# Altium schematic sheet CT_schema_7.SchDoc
size 391 x 238 mm
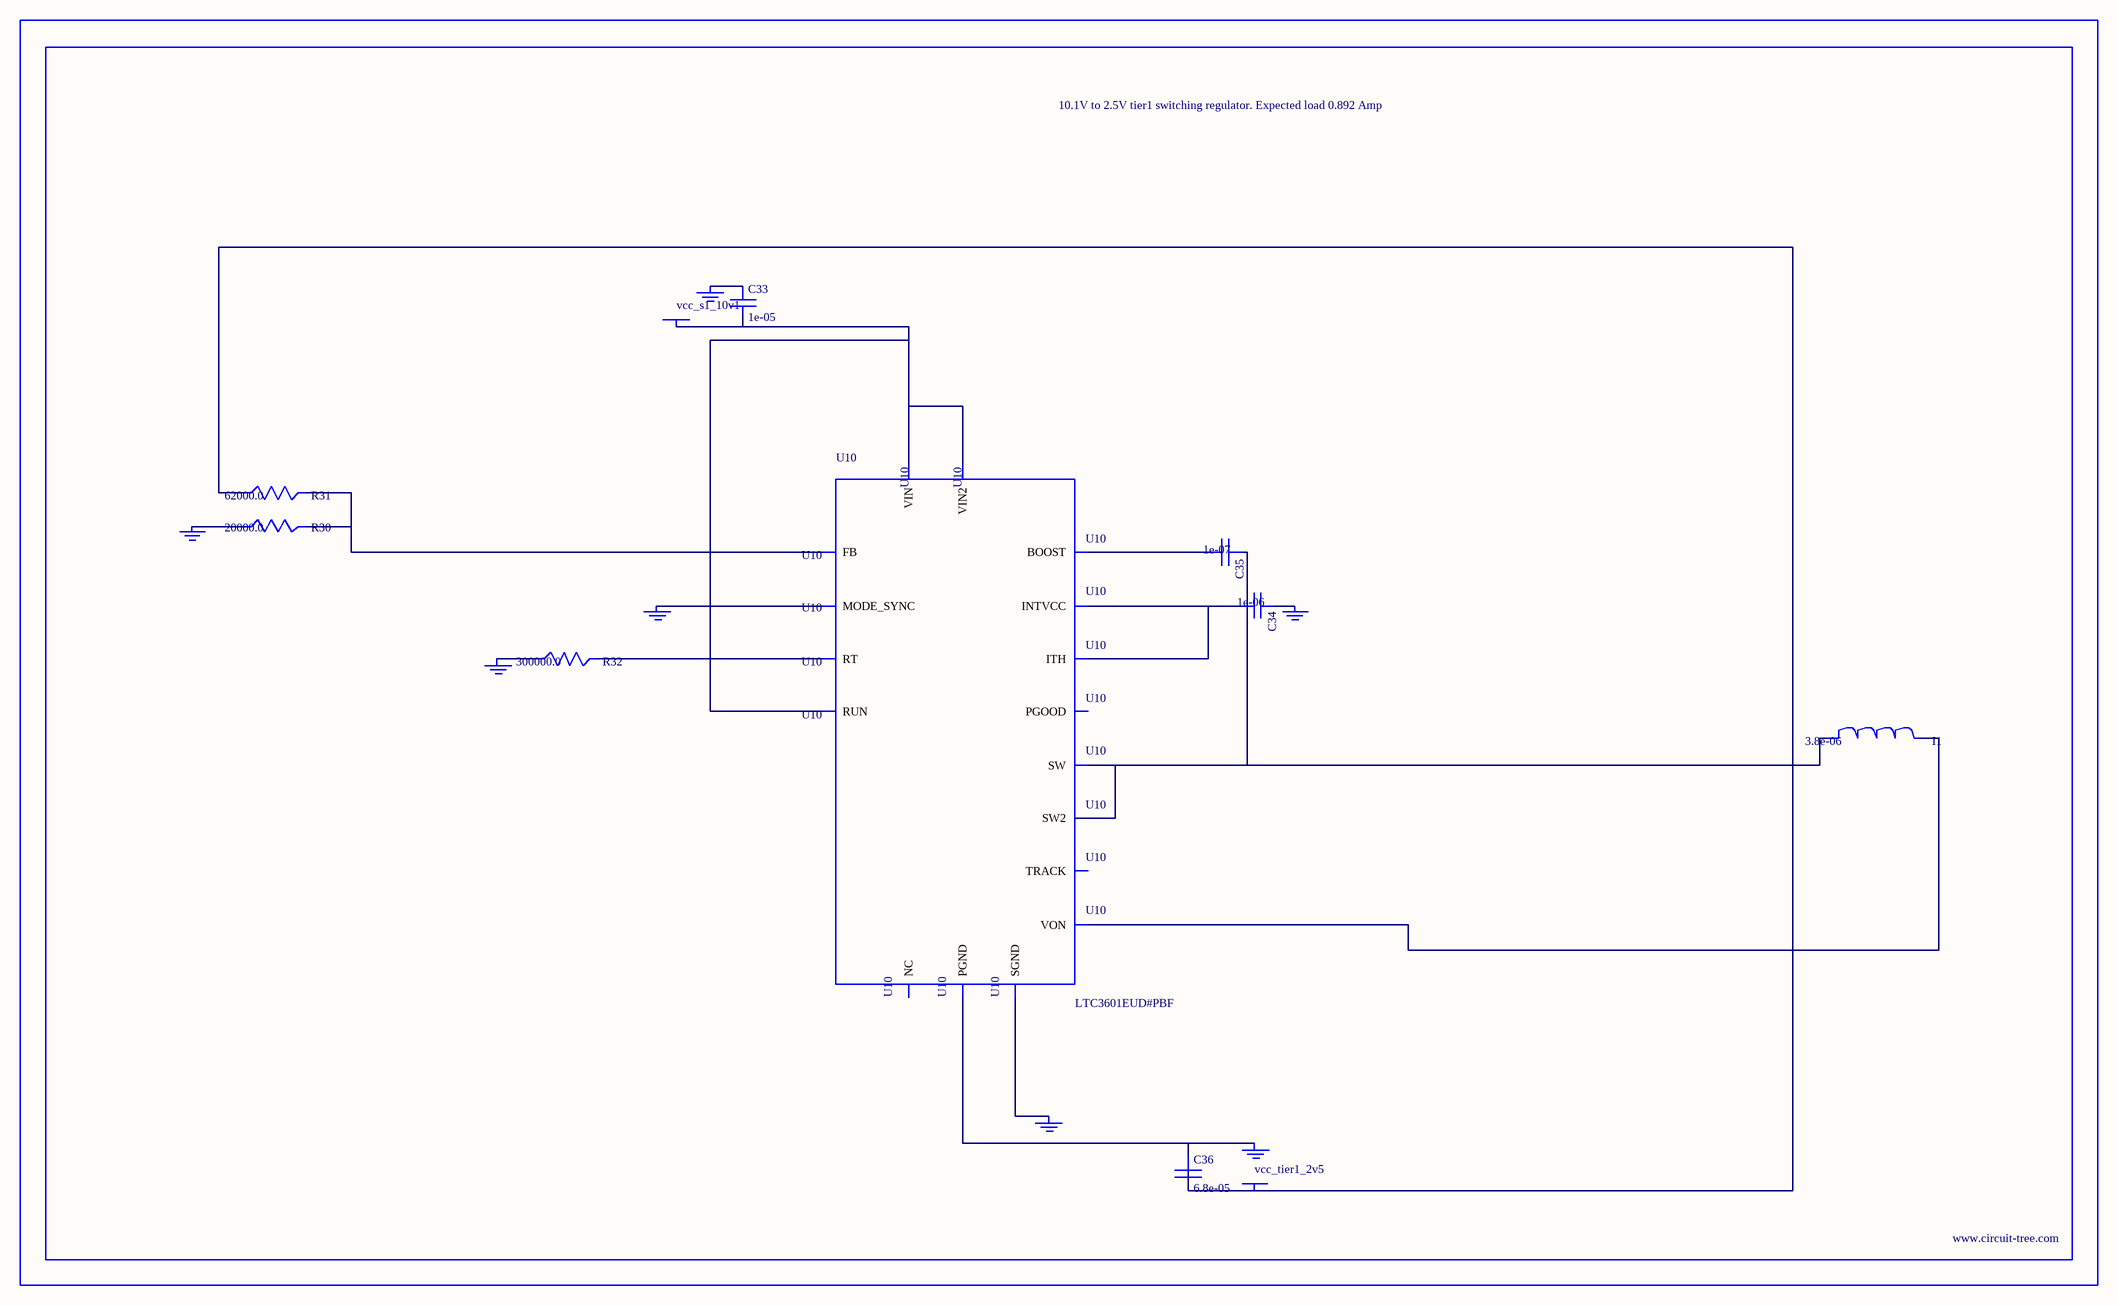
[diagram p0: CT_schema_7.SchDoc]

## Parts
BORDER6  (no value)
C33  1e-05  [C0805]
C34  1e-06  [C0603]
C35  1e-07  [C0402]
C36  6.8e-05  [2220]
GND_INSTANCE_6_0  (no value)
GND_INSTANCE_6_1  (no value)
GND_INSTANCE_6_2  (no value)
GND_INSTANCE_6_3  (no value)
GND_INSTANCE_6_4  (no value)
GND_INSTANCE_6_5  (no value)
GND_INSTANCE_6_6  (no value)
I1  3.8e-06  [DR1040]
POWER_INSTANCE_6_0  vcc_s1_10v1
POWER_INSTANCE_6_1  vcc_tier1_2v5
R30  20000.0  [R0603]
R31  62000.0  [R0603]
R32  300000.0  [R0603]
U10  LTC3601EUD#PBF  [QFN-16_EP]

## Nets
NetC33_1: C33.1 GND_INSTANCE_6_5.0(GND)
NetC33_2: C33.2 POWER_INSTANCE_6_0.0(PWR) U10.14(RUN) U10.15(VIN) U10.16(VIN2)
NetC34_1: C34.1 GND_INSTANCE_6_1.0(GND)
NetC34_2: C34.2 U10.7(INTVCC) U10.12(ITH)
NetC35_1: C35.1 I1.1 U10.3(SW) U10.4(SW2)
NetC35_2: C35.2 U10.6(BOOST)
NetC36_1: C36.1 GND_INSTANCE_6_6.0(GND) U10.17(PGND)
NetC36_2: C36.2 I1.2 POWER_INSTANCE_6_1.0(PWR) R31.1 U10.8(VON)
NetGND_INSTANCE_6_0_0: GND_INSTANCE_6_0.0(GND) U10.1(MODE_SYNC)
NetGND_INSTANCE_6_2_0: GND_INSTANCE_6_2.0(GND) U10.9(SGND)
NetGND_INSTANCE_6_3_0: GND_INSTANCE_6_3.0(GND) R32.1
NetGND_INSTANCE_6_4_0: GND_INSTANCE_6_4.0(GND) R30.1
NetR30_2: R30.2 R31.2 U10.11(FB)
NetR32_2: R32.2 U10.10(RT)

Not connected (* = marked no-connect by the designer): U10 2(PGOOD) 5(NC) 13(TRACK)

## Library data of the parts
BORDER6 = BORDER_PAGE6
C33 = C0805C106K8RACTU
C34 = C0603C105K3RACTU
C35 = C0402C104K3RACTU
C36 = C5750X5R1A686M
GND_INSTANCE_6_0-GND_INSTANCE_6_6 = GND
I1 = DR1040-3R8-R
POWER_INSTANCE_6_0 POWER_INSTANCE_6_1 = PWR
R30 = RC0603JR-0720KL
R31 = RC0603JR-0762KL
R32 = RC0603JR-07300KL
